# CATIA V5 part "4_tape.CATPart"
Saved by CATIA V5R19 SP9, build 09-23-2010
Part number: 4_tape
Revision: ANY
Definition: UNKNOWN
Nomenclature: 4_tape
Source: Unknown
Bounding box of the stored display mesh (mm): x -210 to 210, y 447.505 to 472, z -210 to 210
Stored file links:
  Y:\fin de projet cabestan poupee\4_tape.CATPart
  Ass_arbre poupee_1.CATProduct
  Y:\bricolage cabestan\6_axe.CATPart
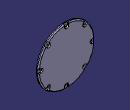
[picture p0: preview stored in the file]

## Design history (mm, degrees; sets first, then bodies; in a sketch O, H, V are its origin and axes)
Body1 "NONE" (main body)
  Solid1: solid without history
